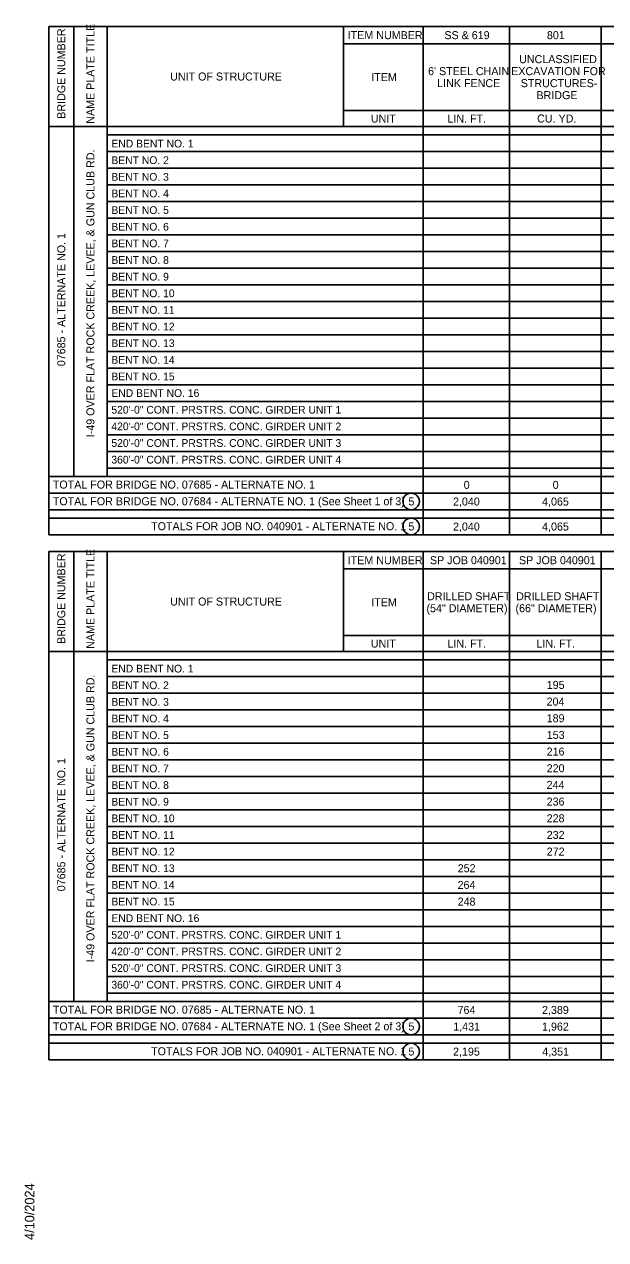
# Model space of a CAD drawing. Extents: x 0.06 to 1.38, y 0.04 to 0.85.
# Drawn here: x 0.06 to 0.423, y 0.079 to 0.838 of the extents above; entities that cross this region are included whole.
import ezdxf

# ---------------------------------------------------------------- set-up
doc = ezdxf.new("R2010")
doc.units = 0
for name, color, linetype in [('R_Shade By Others', 7, 'Continuous'), ('R_Survey Control', 7, 'Continuous'), ('R_Wall', 7, 'Continuous')]:
    doc.layers.add(name, color=color, linetype=linetype)

msp = doc.modelspace()

# ---------------------------------------------------------------- linework, layer by layer
at = {"layer": 'R_Survey Control'}
for p, q in [((0.07508, 0.51924), (0.07508, 0.83695)), ((0.07508, 0.83695), (1.38207, 0.83695)), ((0.09071, 0.5557), (0.09071, 0.83695)), ((0.11154, 0.5557), (0.11154, 0.83695)), ((0.11154, 0.77445), (0.11154, 0.83695)), ((0.2593, 0.77445), (0.2593, 0.83695)), ((0.30915, 0.83695), (0.30915, 0.51924)), ((0.36311, 0.83695), (0.36311, 0.51924)), ((0.4204, 0.83695), (0.4204, 0.51924)), ((0.2593, 0.78445), (1.38207, 0.78445)), ((0.07508, 0.77445), (1.38207, 0.77445)), ((0.11154, 0.76924), (1.38207, 0.76924)), ((0.11154, 0.75883), (1.38207, 0.75883)), ((0.11154, 0.74841), (1.38207, 0.74841)), ((0.11154, 0.73799), (1.38207, 0.73799)), ((0.11154, 0.72758), (1.38207, 0.72758)), ((0.11154, 0.71716), (1.38207, 0.71716)), ((0.11154, 0.70674), (1.38207, 0.70674)), ((0.11154, 0.69633), (1.38207, 0.69633)), ((0.11154, 0.68591), (1.38207, 0.68591)), ((0.11154, 0.67549), (1.38207, 0.67549)), ((0.11154, 0.66508), (1.38207, 0.66508)), ((0.11154, 0.65466), (1.38207, 0.65466)), ((0.11154, 0.64424), (1.38207, 0.64424)), ((0.11154, 0.63383), (1.38207, 0.63383)), ((0.11154, 0.62341), (1.38207, 0.62341)), ((0.11154, 0.61299), (1.38207, 0.61299)), ((0.11154, 0.60258), (1.38207, 0.60258)), ((0.11154, 0.59216), (1.38207, 0.59216)), ((0.11154, 0.58174), (1.38207, 0.58174)), ((0.11154, 0.57133), (1.38207, 0.57133)), ((0.07508, 0.5557), (1.38207, 0.5557)), ((0.11154, 0.56091), (1.38207, 0.56091)), ((0.07508, 0.54529), (1.38207, 0.54529)), ((0.07508, 0.53487), (1.38207, 0.53487)), ((0.07508, 0.52966), (1.38207, 0.52966)), ((0.07508, 0.51924), (1.38207, 0.51924)), ((0.07508, 0.19112), (0.07508, 0.50883)), ((0.07508, 0.50883), (1.30054, 0.50883)), ((0.09071, 0.22758), (0.09071, 0.50883)), ((0.11154, 0.22758), (0.11154, 0.50883)), ((0.11154, 0.44633), (0.11154, 0.50883)), ((0.2593, 0.44633), (0.2593, 0.50883)), ((0.30915, 0.50883), (0.30915, 0.19112)), ((0.36311, 0.50883), (0.36311, 0.19112)), ((0.4204, 0.50883), (0.4204, 0.19112)), ((0.2593, 0.45633), (1.30054, 0.45633)), ((0.07508, 0.44633), (1.30054, 0.44633)), ((0.11154, 0.44112), (1.30054, 0.44112)), ((0.11154, 0.4307), (1.30054, 0.4307)), ((0.11154, 0.42029), (1.30054, 0.42029)), ((0.11154, 0.40987), (1.30054, 0.40987)), ((0.11154, 0.39945), (1.30054, 0.39945)), ((0.11154, 0.38904), (1.30054, 0.38904)), ((0.11154, 0.37862), (1.30054, 0.37862)), ((0.11154, 0.3682), (1.30054, 0.3682)), ((0.11154, 0.35779), (1.30054, 0.35779)), ((0.11154, 0.34737), (1.30054, 0.34737)), ((0.11154, 0.33695), (1.30054, 0.33695)), ((0.11154, 0.32654), (1.30054, 0.32654)), ((0.11154, 0.31612), (1.30054, 0.31612)), ((0.11154, 0.3057), (1.30054, 0.3057)), ((0.11154, 0.29529), (1.30054, 0.29529)), ((0.11154, 0.28487), (1.30054, 0.28487)), ((0.11154, 0.27445), (1.30054, 0.27445)), ((0.11154, 0.26404), (1.30054, 0.26404)), ((0.11154, 0.25362), (1.30054, 0.25362)), ((0.11154, 0.2432), (1.30054, 0.2432)), ((0.11154, 0.23279), (1.30054, 0.23279)), ((0.07508, 0.22758), (1.30054, 0.22758)), ((0.07508, 0.21716), (1.30054, 0.21716)), ((0.07508, 0.20674), (1.30054, 0.20674)), ((0.07508, 0.20154), (1.30054, 0.20154)), ((0.07508, 0.19112), (1.30054, 0.19112))]:
    msp.add_line(p, q, dxfattribs=at)
for points in [[(0.2593, 0.82612), (0.30758, 0.82612), (0.41883, 0.82612), (0.46733, 0.82612), (0.509, 0.82612), (0.60403, 0.82612), (0.64048, 0.82612), (0.68476, 0.82612), (0.72903, 0.82612), (0.79673, 0.82612), (0.84248, 0.82612), (0.89457, 0.82612), (0.99353, 0.82612), (1.05082, 0.82612), (1.11332, 0.82612), (1.24092, 0.82612), (1.249, 0.82612), (1.30109, 0.82612), (1.30109, 0.82612), (1.38207, 0.82612)], [(0.2593, 0.49799), (0.30758, 0.49799), (0.36154, 0.49799), (0.40321, 0.49799), (0.44487, 0.49799), (0.49175, 0.49799), (0.52821, 0.49799), (0.58029, 0.49799), (0.64019, 0.49799), (0.7079, 0.49799), (0.75998, 0.49799), (0.81206, 0.49799), (0.85894, 0.49799), (0.86623, 0.49799), (0.92873, 0.49799), (0.99644, 0.49799), (1.06415, 0.49799), (1.11623, 0.49799), (1.16831, 0.49799), (1.30054, 0.49799)]]:
    msp.add_lwpolyline(points, dxfattribs=at)
at = {"layer": 'R_Wall'}
for p, q in [((0.07508, 0.77445), (0.09071, 0.77445)), ((0.09071, 0.77445), (0.11154, 0.77445)), ((0.07508, 0.44633), (0.09071, 0.44633)), ((0.09071, 0.44633), (0.11154, 0.44633))]:
    msp.add_line(p, q, dxfattribs=at)
for centre in [(0.30155, 0.54014), (0.30155, 0.52451), (0.30155, 0.21201), (0.30155, 0.19639)]:
    msp.add_circle(centre, 0.00515, dxfattribs=at)

# ---------------------------------------------------------------- texts
at = {"layer": 'R_Shade By Others'}
msp.add_text('4/10/2024', height=0.00595, rotation=89.99995, dxfattribs=at).set_placement((0.06607, 0.0786))
at = {"layer": 'R_Survey Control'}
for s, p in [('NAME PLATE TITLE', (0.10362, 0.77619)), ('BRIDGE NUMBER', (0.0854, 0.77929)), ('I-49 OVER FLAT ROCK CREEK, LEVEE, & GUN CLUB RD.', (0.10362, 0.58025)), ('07685 - ALTERNATE NO. 1', (0.0854, 0.62465)), ('NAME PLATE TITLE', (0.10362, 0.44806)), ('BRIDGE NUMBER', (0.0854, 0.45116)), ('I-49 OVER FLAT ROCK CREEK, LEVEE, & GUN CLUB RD.', (0.10362, 0.25212)), ('07685 - ALTERNATE NO. 1', (0.0854, 0.29652))]:
    msp.add_text(s, height=0.005, rotation=90, dxfattribs=at).set_placement(p)
for s, height, p in [('ITEM NUMBER', 0.005, (0.26194, 0.82904)), ('SS & 619', 0.005, (0.32235, 0.82904)), ('801', 0.005, (0.3864, 0.82904)), ('UNCLASSIFIED', 0.005, (0.36903, 0.81404)), ('UNIT OF STRUCTURE', 0.005, (0.15095, 0.8032)), ('ITEM', 0.005, (0.27661, 0.80279)), ("6' STEEL CHAIN", 0.005, (0.31212, 0.80654)), ('EXCAVATION FOR ', 0.005, (0.36408, 0.80654)), ('LINK FENCE', 0.005, (0.31785, 0.79904)), ('STRUCTURES-', 0.005, (0.37004, 0.79904)), ('BRIDGE', 0.005, (0.37987, 0.79154)), ('UNIT', 0.005, (0.27638, 0.77695)), ('LIN. FT.', 0.005, (0.32421, 0.77695)), ('CU. YD.', 0.005, (0.38029, 0.77695)), ('END BENT NO. 1', 0.0048358, (0.11421, 0.76137)), ('BENT NO. 2', 0.004836, (0.11421, 0.75098)), ('BENT NO. 3', 0.004836, (0.11421, 0.74058)), ('BENT NO. 4', 0.004836, (0.11421, 0.73018)), ('BENT NO. 5', 0.004836, (0.11421, 0.71979)), ('BENT NO. 6', 0.004836, (0.11421, 0.70939)), ('BENT NO. 7', 0.004836, (0.11421, 0.69899)), ('BENT NO. 8', 0.004836, (0.11421, 0.6886)), ('BENT NO. 9', 0.004836, (0.11421, 0.6782)), ('BENT NO. 10', 0.0048358, (0.11421, 0.6678)), ('BENT NO. 11', 0.0048358, (0.11421, 0.65741)), ('BENT NO. 12', 0.0048358, (0.11421, 0.64701)), ('BENT NO. 13', 0.0048358, (0.11421, 0.63661)), ('BENT NO. 14', 0.0048358, (0.11421, 0.62621)), ('BENT NO. 15', 0.0048358, (0.11421, 0.61582)), ('END BENT NO. 16', 0.0048358, (0.11421, 0.60542)), ('520\'-0" CONT. PRSTRS. CONC. GIRDER UNIT 1', 0.0048358, (0.11421, 0.59502)), ('420\'-0" CONT. PRSTRS. CONC. GIRDER UNIT 2', 0.0048358, (0.11421, 0.58463)), ('520\'-0" CONT. PRSTRS. CONC. GIRDER UNIT 3', 0.0048358, (0.11421, 0.57423)), ('360\'-0" CONT. PRSTRS. CONC. GIRDER UNIT 4', 0.0048358, (0.11421, 0.56383)), ('TOTAL FOR BRIDGE NO. 07685 - ALTERNATE NO. 1', 0.005, (0.07763, 0.54818)), ('0', 0.005, (0.33439, 0.54799)), ('0', 0.005, (0.39001, 0.54799)), ('TOTAL FOR BRIDGE NO. 07684 - ALTERNATE NO. 1 (See Sheet 1 of 3)', 0.005, (0.07763, 0.53776)), ('2,040', 0.005, (0.32772, 0.53758)), ('4,065', 0.005, (0.38339, 0.53758)), ('TOTALS FOR JOB NO. 040901 - ALTERNATE NO. 1', 0.005, (0.13905, 0.52216)), ('2,040', 0.005, (0.32772, 0.52195)), ('4,065', 0.005, (0.38339, 0.52195)), ('ITEM NUMBER', 0.005, (0.26194, 0.50091)), ('SP JOB 040901', 0.005, (0.3133, 0.50091)), ('SP JOB 040901', 0.005, (0.36892, 0.50091)), ('UNIT OF STRUCTURE', 0.005, (0.15095, 0.47508)), ('ITEM', 0.005, (0.27661, 0.47466)), ('DRILLED SHAFT', 0.005, (0.31153, 0.47841)), ('DRILLED SHAFT', 0.005, (0.36715, 0.47841)), ('(54" DIAMETER)', 0.005, (0.31114, 0.47091)), ('(66" DIAMETER)', 0.005, (0.36677, 0.47091)), ('UNIT', 0.005, (0.27638, 0.44883)), ('LIN. FT.', 0.005, (0.32421, 0.44883)), ('LIN. FT.', 0.005, (0.37983, 0.44883)), ('END BENT NO. 1', 0.0048358, (0.11421, 0.43325)), ('BENT NO. 2', 0.004836, (0.11421, 0.42285)), ('195', 0.005, (0.3863, 0.42299)), ('BENT NO. 3', 0.004836, (0.11421, 0.41246)), ('204', 0.005, (0.38621, 0.41258)), ('BENT NO. 4', 0.004836, (0.11421, 0.40206)), ('189', 0.005, (0.38627, 0.40216)), ('BENT NO. 5', 0.004836, (0.11421, 0.39166)), ('153', 0.005, (0.38632, 0.39174)), ('BENT NO. 6', 0.004836, (0.11421, 0.38127)), ('216', 0.005, (0.38624, 0.38133)), ('BENT NO. 7', 0.004836, (0.11421, 0.37087)), ('220', 0.005, (0.38626, 0.37091)), ('BENT NO. 8', 0.004836, (0.11421, 0.36047)), ('244', 0.005, (0.38621, 0.36049)), ('BENT NO. 9', 0.004836, (0.11421, 0.35007)), ('236', 0.005, (0.38624, 0.35008)), ('BENT NO. 10', 0.0048358, (0.11421, 0.33968)), ('228', 0.005, (0.38625, 0.33966)), ('232', 0.005, (0.38628, 0.32924)), ('BENT NO. 11', 0.0048358, (0.11421, 0.32928)), ('BENT NO. 12', 0.0048358, (0.11421, 0.31888)), ('272', 0.005, (0.38628, 0.31883)), ('BENT NO. 13', 0.0048358, (0.11421, 0.30849)), ('252', 0.005, (0.33065, 0.30841)), ('BENT NO. 14', 0.0048358, (0.11421, 0.29809)), ('264', 0.005, (0.33058, 0.29799)), ('BENT NO. 15', 0.0048358, (0.11421, 0.28769)), ('248', 0.005, (0.33062, 0.28758)), ('END BENT NO. 16', 0.0048358, (0.11421, 0.2773)), ('520\'-0" CONT. PRSTRS. CONC. GIRDER UNIT 1', 0.0048358, (0.11421, 0.2669)), ('420\'-0" CONT. PRSTRS. CONC. GIRDER UNIT 2', 0.0048358, (0.11421, 0.2565)), ('520\'-0" CONT. PRSTRS. CONC. GIRDER UNIT 3', 0.0048358, (0.11421, 0.2461)), ('360\'-0" CONT. PRSTRS. CONC. GIRDER UNIT 4', 0.0048358, (0.11421, 0.23571)), ('TOTAL FOR BRIDGE NO. 07685 - ALTERNATE NO. 1', 0.005, (0.07763, 0.22006)), ('764', 0.005, (0.33058, 0.21987)), ('2,389', 0.005, (0.38335, 0.21987)), ('TOTAL FOR BRIDGE NO. 07684 - ALTERNATE NO. 1 (See Sheet 2 of 3)', 0.005, (0.07763, 0.20964)), ('1,431', 0.005, (0.32786, 0.20945)), ('1,962', 0.005, (0.38336, 0.20945)), ('TOTALS FOR JOB NO. 040901 - ALTERNATE NO. 1', 0.005, (0.13905, 0.19403)), ('2,195', 0.005, (0.32776, 0.19383)), ('4,351', 0.005, (0.38348, 0.19383))]:
    msp.add_text(s, height=height, dxfattribs=at).set_placement(p)
at = {"layer": 'R_Wall'}
for p in [(0.29985, 0.53764), (0.29985, 0.52201), (0.29985, 0.20951), (0.29985, 0.19389)]:
    msp.add_text('5', height=0.005, dxfattribs=at).set_placement(p)

doc.saveas('drawing.dxf')
